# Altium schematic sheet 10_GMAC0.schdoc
size 302 x 215 mm; Symbol: Sheet_A4; Device: Sheet_A4; @Project Name: Avaota A1; Company: YuzukiHD; Version: 1.0; @Page No: 11; @Page Count: 13; @Update Date: 2024-02-27; Comment: GloomyGhost
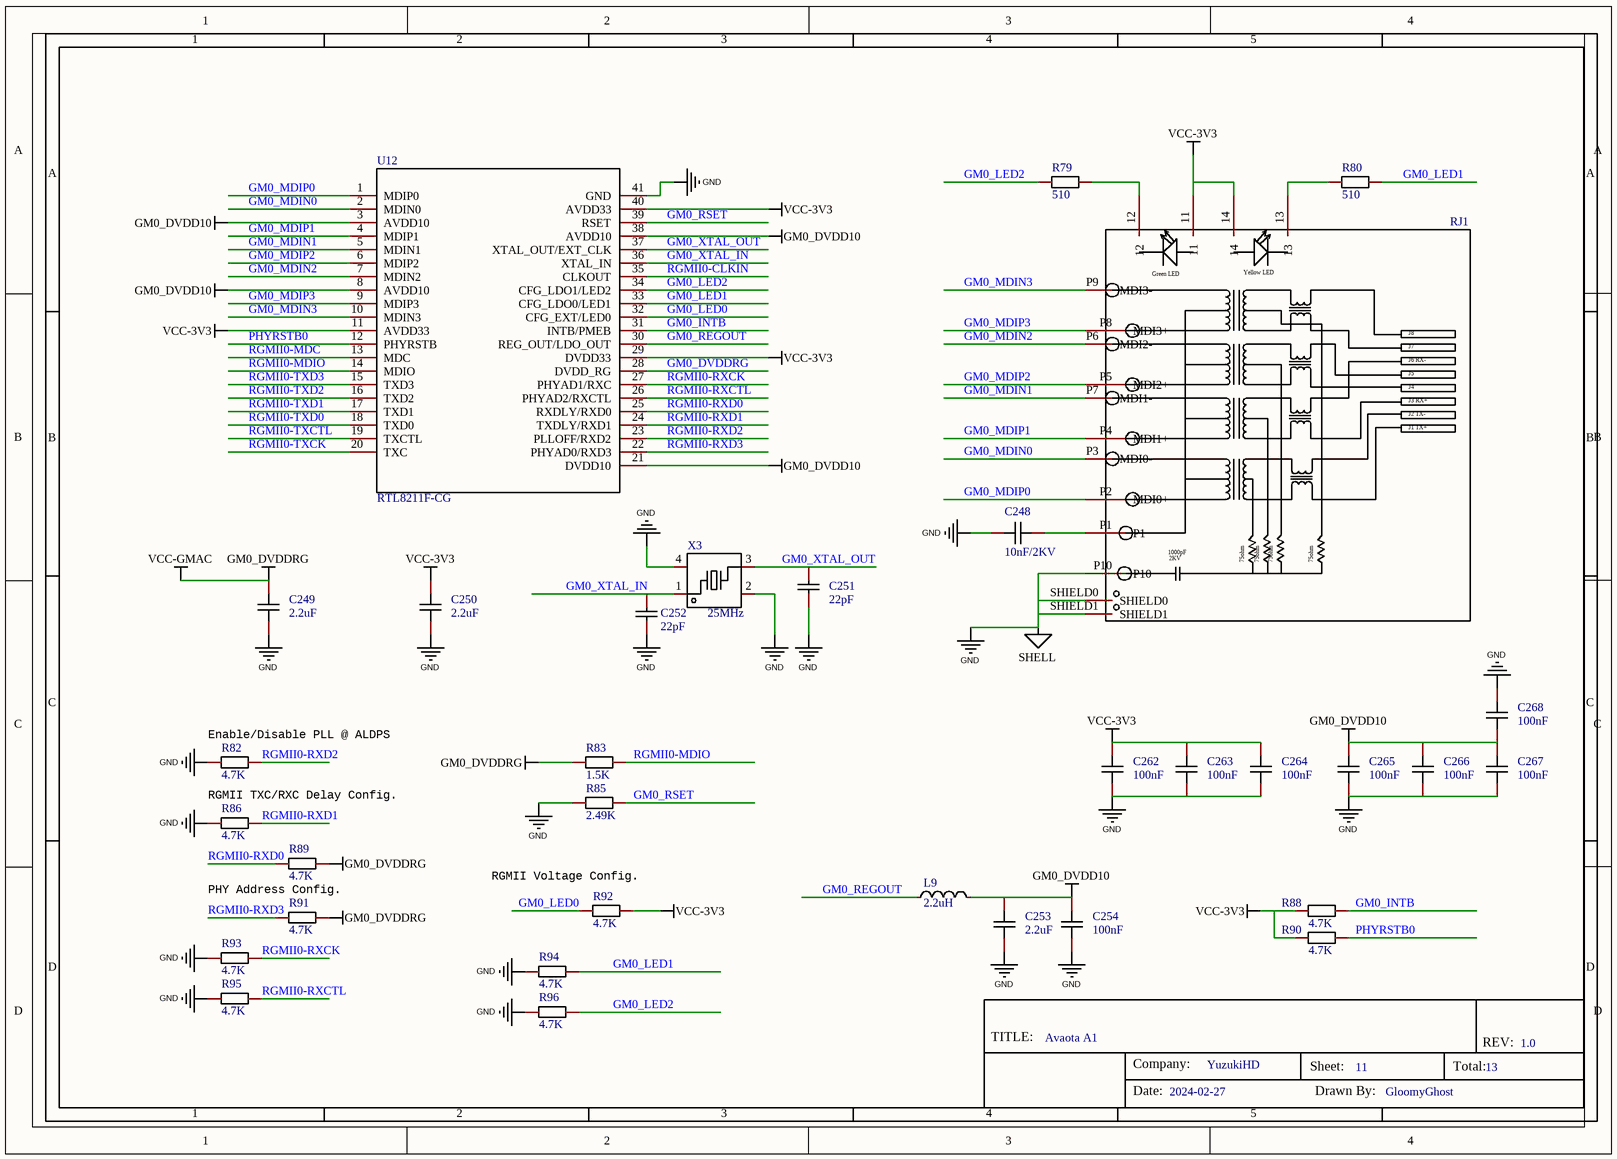
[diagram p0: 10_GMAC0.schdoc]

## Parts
C248  10nF/2KV  [C1206]
C249  2.2uF  [c0201 nsk]
C250  2.2uF  [c0201 nsk]
C251  22pF  [c0201 nsk]
C252  22pF  [c0201 nsk]
C253  2.2uF  [c0201 nsk]
C254  100nF  [c0201 nsk]
C262  100nF  [c0201 nsk]
C263  100nF  [c0201 nsk]
C264  100nF  [c0201 nsk]
C265  100nF  [c0201 nsk]
C266  100nF  [c0201 nsk]
C267  100nF  [c0201 nsk]
C268  100nF  [c0201 nsk]
L9  2.2uH  [IND-SMD_L2.0-W1.6]
R79  510  [r0201 nsk]
R80  510  [r0201 nsk]
R82  4.7K  [r0201 nsk]
R83  1.5K  [r0201 nsk]
R85  2.49K  [r0201 nsk]
R86  4.7K  [r0201 nsk]
R88  4.7K  [r0201 nsk]
R89  4.7K  [r0201 nsk]
R90  4.7K  [r0201 nsk]
R91  4.7K  [r0201 nsk]
R92  4.7K  [r0201 nsk]
R93  4.7K  [r0201 nsk]
R94  4.7K  [r0201 nsk]
R95  4.7K  [r0201 nsk]
R96  4.7K  [r0201 nsk]
RJ1  HR911130A  [RJ45-TH_HR911130A]  (value not drawn)
U12  RTL8211F-CG  [WQFN-40_L5.0-W5.0-P0.4-BL-EP]
X3  25MHz  [crystal-smd_4p-l2.0-w1.6-bl-nsk]

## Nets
GM0_DVDD10: C253.1 C254.1 C265.1 C266.1 C267.1 C268.2 L9.2 U12.3(AVDD10) U12.8(AVDD10) U12.21(DVDD10) U12.38(AVDD10)
GM0_DVDDRG: C249.1 R83.1 R89.2 R91.2 U12.28(DVDD_RG)  [also labelled VCC-GMAC]
GND: C248.1 C249.2 C250.2 C251.1 C252.1 C253.2 C254.2 C262.2 C263.2 C264.2 C265.2 C266.2 C267.2 C268.1 R82.1 R85.1 R86.1 R93.1 R94.1 R95.1 R96.1 RJ1.P10 RJ1.SHIELD0 RJ1.SHIELD1 U12.41(GND) X3.2(GND) X3.4(GND)  [also labelled SHELL]
VCC-3V3: C250.1 C262.1 C263.1 C264.1 R88.1 R90.1 R92.2 RJ1.11 RJ1.14 U12.11(AVDD33) U12.29(DVDD33) U12.40(AVDD33)
GM0_INTB: R88.2 U12.31(INTB/PMEB)
GM0_LED0: R92.1 U12.32(CFG_EXT/LED0)
GM0_LED1: R80.2 R94.2 U12.33(CFG_LDO0/LED1)
GM0_LED2: R79.1 R96.2 U12.34(CFG_LDO1/LED2)
GM0_MDIN0: RJ1.P3(MDI0-) U12.2(MDIN0)
GM0_MDIN1: RJ1.P7(MDI1-) U12.5(MDIN1)
GM0_MDIN2: RJ1.P6(MDI2-) U12.7(MDIN2)
GM0_MDIN3: RJ1.P9(MDI3-) U12.10(MDIN3)
GM0_MDIP0: RJ1.P2(MDI0+) U12.1(MDIP0)
GM0_MDIP1: RJ1.P4(MDI1+) U12.4(MDIP1)
GM0_MDIP2: RJ1.P5(MDI2+) U12.6(MDIP2)
GM0_MDIP3: RJ1.P8(MDI3+) U12.9(MDIP3)
GM0_REGOUT: L9.1 U12.30(REG_OUT/LDO_OUT)
GM0_RSET: R85.2 U12.39(RSET)
GM0_XTAL_IN: C252.2 U12.36(XTAL_IN) X3.1(IN)
GM0_XTAL_OUT: C251.2 U12.37(XTAL_OUT/EXT_CLK) X3.3(OUT)
PHYRSTB0: R90.2 U12.12(PHYRSTB)
RGMII0-CLKIN: U12.35(CLKOUT)
RGMII0-MDC: U12.13(MDC)
RGMII0-MDIO: R83.2 U12.14(MDIO)
RGMII0-RXCK: R93.2 U12.27(PHYAD1/RXC)
RGMII0-RXCTL: R95.2 U12.26(PHYAD2/RXCTL)
RGMII0-RXD0: R89.1 U12.25(RXDLY/RXD0)
RGMII0-RXD1: R86.2 U12.24(TXDLY/RXD1)
RGMII0-RXD2: R82.2 U12.23(PLLOFF/RXD2)
RGMII0-RXD3: R91.1 U12.22(PHYAD0/RXD3)
RGMII0-TXCK: U12.20(TXC)
RGMII0-TXCTL: U12.19(TXCTL)
RGMII0-TXD0: U12.18(TXD0)
RGMII0-TXD1: U12.17(TXD1)
RGMII0-TXD2: U12.16(TXD2)
RGMII0-TXD3: U12.15(TXD3)
NetC248_2: C248.2 RJ1.P1
NetR79_2: R79.2 RJ1.12
NetR80_1: R80.1 RJ1.13

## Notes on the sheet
- (near R82) Enable/Disable PLL @ ALDPS
- RGMII TXC/RXC Delay Config.
- PHY Address Config.
- (near R92) RGMII Voltage Config.

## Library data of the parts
C248 = CAP_1206: Symbol: CapAcitance; Convert to PCB: yes
C249 C250 C253 C254 C262-C268 = 0201X225M6R3NT: Manufacturer: FH(风华); Add into BOM: yes; Tolerance: ±20%; Voltage Rated: 6.3V; Temperature Coefficient: X5R; Description: 容值:2.2uF;精度:±20%;额定电压:6.3V;材质(温度系数):X5R;
C251 C252 = 0201CG220J500NT: Manufacturer: FH(风华); Add into BOM: yes; Tolerance: ±5%; Voltage Rated: 50V; Temperature Coefficient: C0G; Description: 容值:22pF;精度:±5%;额定电压:50V;材质(温度系数):C0G;
L9 = WPN252012H2R2MT: Manufacturer: Sunlord(顺络); Add into BOM: yes; Tolerance: ±20%; Rated Current: 1.9A; Saturation Current (Isat): 3A; DC Resistance (DCR): 120mΩ; Description: 电感值:2.2uH;精度:±20%;额定电流:1.9A;饱和电流(Isat):3A;类型:-;
R79 R80 R82 R83 R85 R86 R88-R96 = Res_0201: Symbol: 电阻; Convert to PCB: yes
RJ1 = HR911130A: Manufacturer: HANRUN(汉仁); Add into BOM: yes; Connector Type: RJ插座; USOC Codes: RJ45; Number of Ports: 1; LED: 有; Description: 连接器类型:RJ插座;USOC代码:RJ45;端口数量:1;等级:-;屏蔽:-;LED:有;
U12 = RTL8211F-CG: Manufacturer: REALTEK(瑞昱); Add into BOM: yes; Description: 应用功能:-;通道数:-;接口类型:-;
X3 = 7D025000Q01: Manufacturer: HD(浩都频率); Add into BOM: yes; Crystal Type: 贴片晶振; Normal temperature Frequency Tolerance: ±10ppm; External load capacitor: 18pF; Frequency Stability(Full temperature range): ±20ppm; Description: 晶振类型:贴片晶振;频率:25MHz;常温频差:±10ppm;外接负载电容:18pF;频率稳定度(全温):±20ppm;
